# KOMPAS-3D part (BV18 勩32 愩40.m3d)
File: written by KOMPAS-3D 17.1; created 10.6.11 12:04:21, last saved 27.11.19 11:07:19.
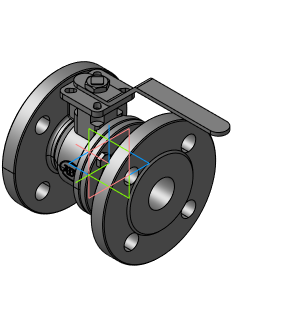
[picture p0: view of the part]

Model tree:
1. Плоскость XY
2. Плоскость ZX
3. Плоскость ZY
4. Ось X
5. Ось Y
6. Ось Z
7. Начало координат
8. Операция без истории:6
